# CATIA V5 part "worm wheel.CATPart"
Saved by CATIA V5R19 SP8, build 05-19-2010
Part number: worm wheel
Bounding box of the stored display mesh (mm): x -12 to 8, y 121.015 to 139.185, z -24.207 to -5.153
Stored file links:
  G:\EU_thinkMotion\CFAO_2010\MMS_groupe1\MMS_groupe1\A reprendre\gduval\CFAO kinematic ok\worm wheel.CATPart
  C:\Users\guillaume\ecole\Cours IFMA\S3\CFAO\brevet Think motion\CATIA\skeleton endless screw-worm drive.CATPart
  G:\EU_thinkMotion\CFAO_2010\MMS_groupe1\MMS_groupe1\A reprendre\gduval\CFAO kinematic ok\threated spindled.CATPart
  C:\Users\guillaume\ecole\Cours IFMA\S3\CFAO\brevet Think motion\CATIA\skeleton worm wheel.CATPart
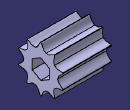
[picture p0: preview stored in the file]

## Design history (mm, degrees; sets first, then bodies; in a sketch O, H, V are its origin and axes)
Body1 (main body)
  Plane1: stored without definition
  Plane2: stored without definition
  Point1: stored without definition
  Point2: stored without definition
  Line1: type PtPt, FirstPoint Point2, SecondPoint Point1
  Plane3: stored without definition
  Sketch1 on Plane2, origin (-12, 0, 0), H (0, 1, 0), V (0, 0, 1)
    spline S1 through (130.0207, -5.1535) (129.9319, -5.191) (129.6653, -5.537) (129.4268, -6.159) (129.0823, -6.9998) (128.7189, -7.5145) (127.9285, -7.9968)
    line L1 (127.9285, -7.9968) -> (130.1, -14.68)
    point P1 (127.9285, -7.9968)
    point P2 (130.1, -14.68)
    reference projected point E1 (130.1, -14.68) from Line1
    axis line L2 (130.1, -14.68) -> (130.1, -2.0775)
    reference projected point E2 (130.1, -14.68) from Line1
    arc A1 centre (130.1, -14.68) radius 9.5268 from (130.1, -5.1532) to (130.0207, -5.1535) ccw
    point P5 (130.0207, -5.1535)
    point P6 (130.1, -5.1532)
    spline S2 through (130.1793, -5.1535) (130.2681, -5.191) (130.5347, -5.537) (130.7732, -6.159) (131.1177, -6.9998) (131.4811, -7.5145) (132.2715, -7.9968)
    point P7 (130.1, -14.68)
    point P8 (132.2715, -7.9968)
    line L3 (132.2715, -7.9968) -> (130.1, -14.68)
    point P9 (130.1793, -5.1535)
    point P10 (130.1, -5.1532)
    arc A2 centre (130.1, -14.68) radius 9.5268 from (130.1, -5.1532) to (130.1793, -5.1535) cw
    point P12 (127.9285, -7.9968)
    point P13 (130.0207, -5.1535)
    point P14 (132.2715, -7.9968)
    point P15 (130.1793, -5.1535)
    point P16 (128.7189, -7.5145)
    point P17 (131.4811, -7.5145)
    point P18 (129.0823, -6.9998)
    point P19 (131.1177, -6.9998)
    point P20 (129.4268, -6.159)
    point P21 (130.7732, -6.159)
    point P22 (129.6653, -5.537)
    point P23 (130.5347, -5.537)
    point P24 (129.9319, -5.191)
    point P25 (130.2681, -5.191)
    angle L1 L2 = 18
    coincidence: E1 P2, P12 P1, L2 E2, P13 P5, P6 L2, P2 P7, P6 P10, P15 P9, P14 P8
    vertical: L2 V
    symmetry: S1 S2 L2, P2 P7 L2, P1 P8 L2, L1 L3 L2, P5 P9 L2, P6 P10 L2, A1 A2 L2, P12 P14 L2, P13 P15 L2, P16 P17 L2, P18 P19 L2, P20 P21 L2, P22 P23 L2, P24 P25 L2
  Pad1: profile Sketch1, direction (1, 0, 0), up to Plane1
  CircPattern1: of Pad1, instances 10, angular step 36, axis from Line1
  Sketch2 on face of CircPattern1, origin (-12, 0, 0), H (0, -1, 0), V (0, 0, 1)
    point P1 (-130.1, -14.68)
    point P2 (-126.6, -12.6593)
    point P3 (-130.1, -10.6385)
    point P4 (-133.6, -12.6593)
    point P5 (-133.6, -16.7007)
    point P6 (-130.1, -18.7215)
    point P7 (-126.6, -16.7007)
    point P8 (-128.35, -11.6489)
    line L1 (-126.6, -12.6593) -> (-130.1, -10.6385)
    line L2 (-130.1, -10.6385) -> (-133.6, -12.6593)
    line L3 (-133.6, -12.6593) -> (-133.6, -16.7007)
    line L4 (-133.6, -16.7007) -> (-130.1, -18.7215)
    line L5 (-130.1, -18.7215) -> (-126.6, -16.7007)
    line L6 (-126.6, -16.7007) -> (-126.6, -12.6593)
    construction line L7 (-130.1, -14.68) -> (-128.35, -11.6489)
    construction circle A1 centre (-130.1, -14.68) radius 4.0415
    construction arc A2 centre (-130.1, -18.7215) radius 4.0415 from (-133.6, -16.7007) to (-126.6, -16.7007) cw
    construction arc A3 centre (-130.1, -10.6385) radius 4.0415 from (-133.6, -12.6593) to (-126.6, -12.6593) ccw
    reference projected point E1 (-130.1, -14.68) from Line1
    axis line L8 (-130.1, -14.68) -> (-130.1, -10.6385)
    distance L1 L4 = 7
    coincidence: A1 P2, A1 P3, A1 P4, A1 P5, A1 P6, A1 P7, A2 P1, A3 P1, P1 E1
    midpoint: P8 L1
    parallelism: L8 L3
    vertical: L8 V
  Pocket1: profile Sketch2, direction (1, 0, 0), through (limit type 6)
  Plane4: type OffsetPt, RefPlane xy-plane, RefPoint Point1
  Line2: type PtDir, RefPoint Point1, Direction Plane4, Start -20, End 30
